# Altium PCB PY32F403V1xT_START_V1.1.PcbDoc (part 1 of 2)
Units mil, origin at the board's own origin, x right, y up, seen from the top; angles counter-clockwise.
Board outline 1771.65 x 2660.63 mil, 2 copper layers (Top Layer, Bottom Layer); 52 components, 105 nets, 324 pads, 111 vias.
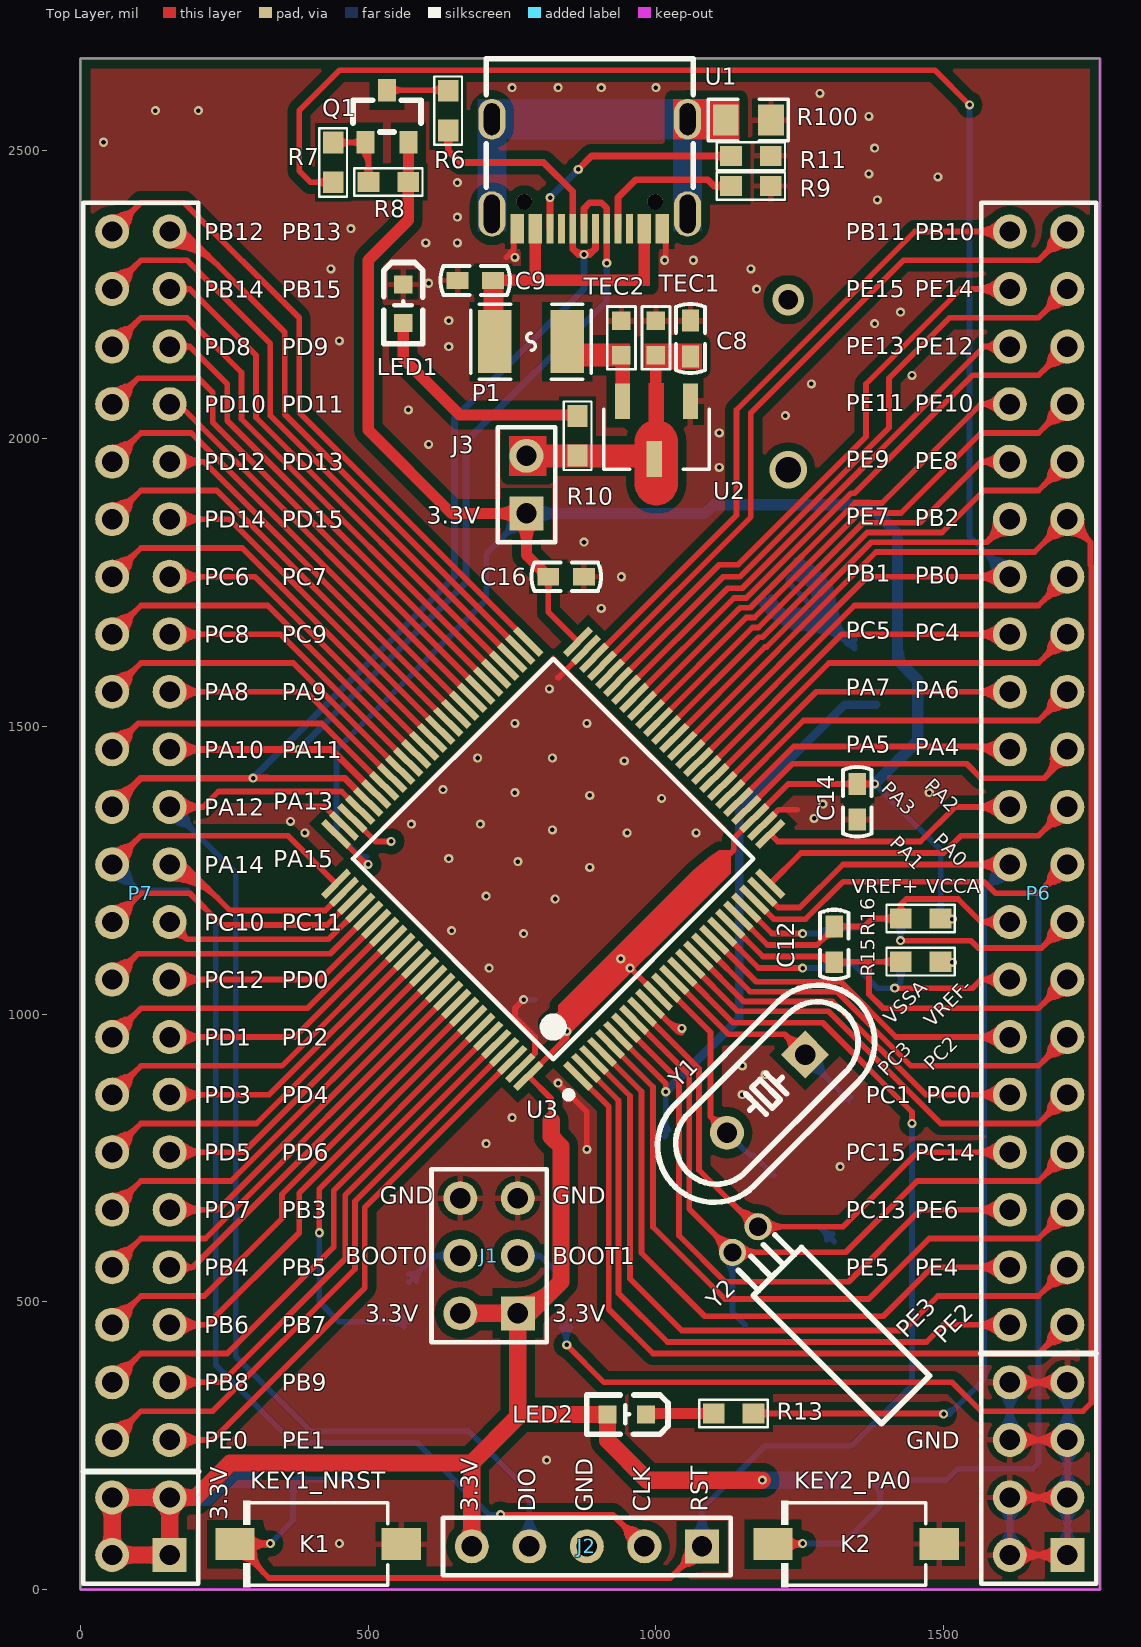
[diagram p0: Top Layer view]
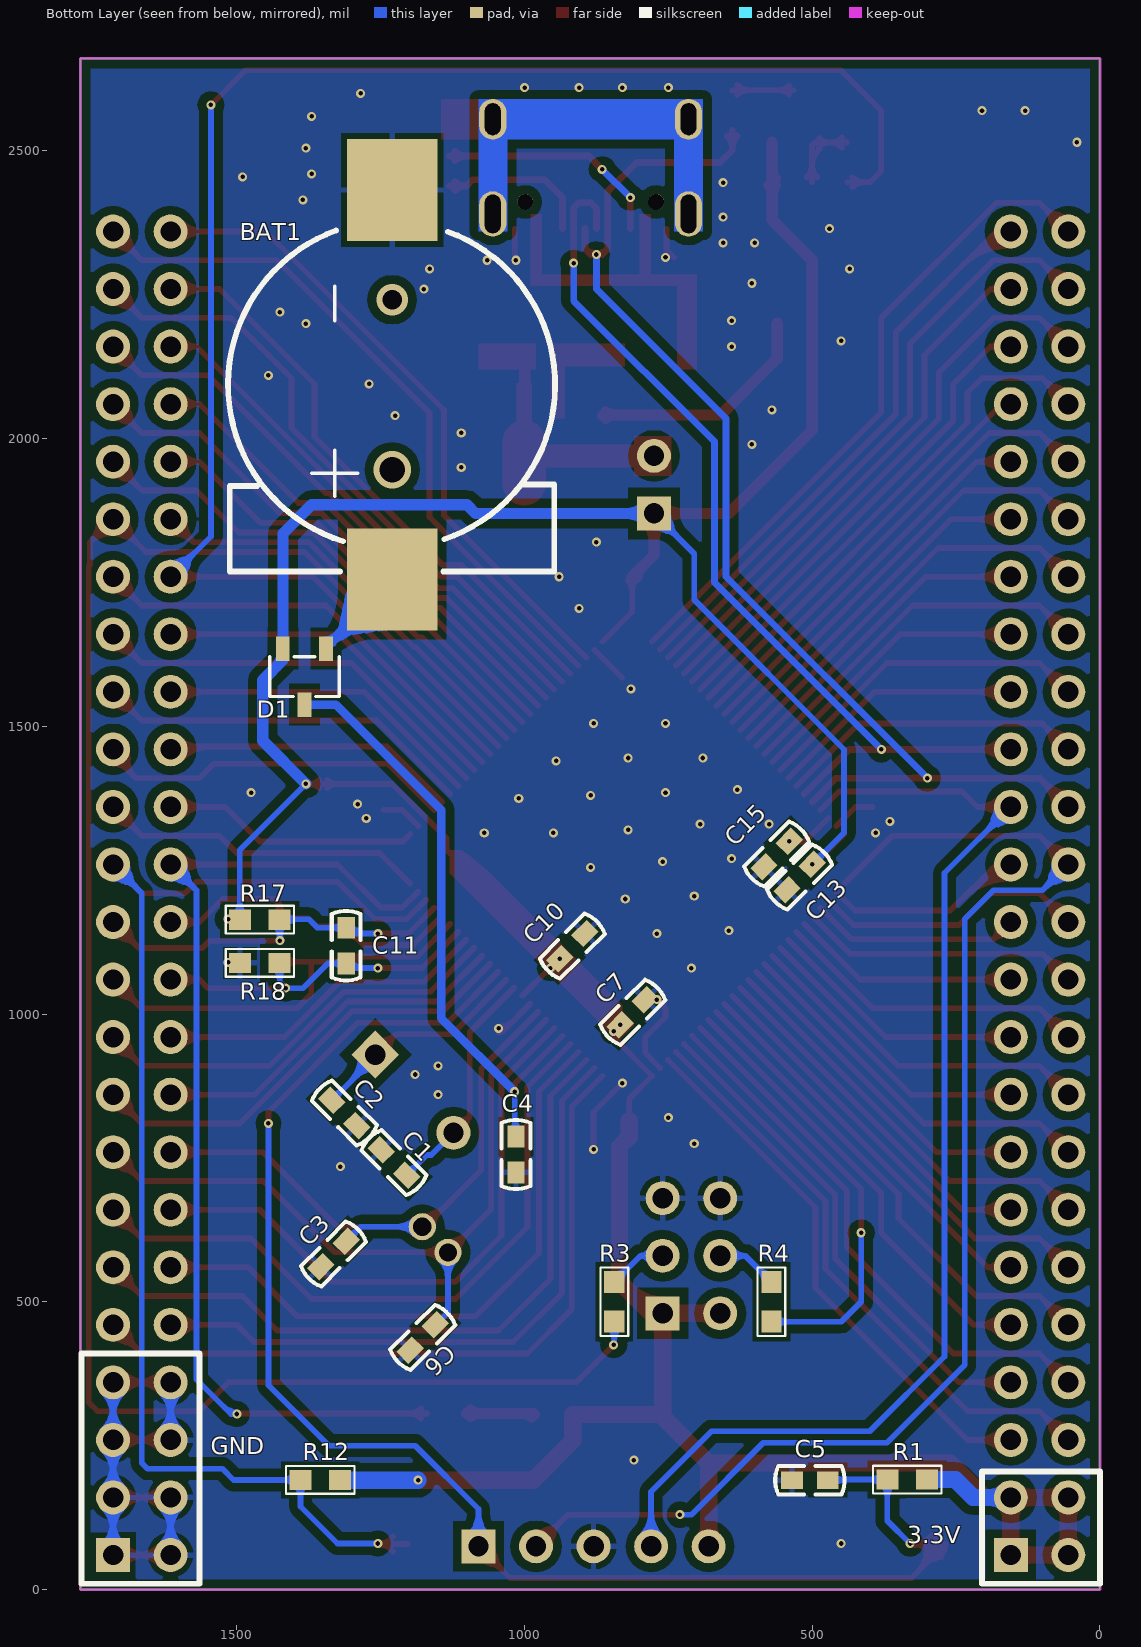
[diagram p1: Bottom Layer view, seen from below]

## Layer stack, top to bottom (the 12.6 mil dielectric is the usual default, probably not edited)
Top Layer: signal copper 1.4
Dielectric: dielectric 12.6, FR-4, Dk 4.8
Bottom Layer: signal copper 1.4

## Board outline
0,0 1771.65,0 1771.65,2660.63 0,2660.63

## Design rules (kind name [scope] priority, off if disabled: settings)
Clearance [All] p1: gap=7
ComponentClearance [All] p1: gap=0 collisioncheckmode=3 verticalgap=0 showdistances=FALSE
HoleSize [All] p1: absolutevalues=TRUE maxlimit=100 minlimit=0 maxpercent=80.000 minpercent=20.000
HoleToHoleClearance [All] p1: gap=0 allowstackedmicrovias=TRUE
MinimumSolderMaskSliver [All] p1: minsoldermaskwidth=0
PolygonConnect PolygonConnect_1 [IsVia] p1: connectstyle=Direct reliefconductorwidth=10 reliefentries=4 polygonreliefangle="90 Angle" airgapwidth=10
PolygonConnect [All] p2: connectstyle=Relief reliefconductorwidth=10 reliefentries=4 polygonreliefangle="90 Angle" airgapwidth=10
RoutingVias [All] p1: holewidth=7.87 width=15.75 viastyle="Through Hole" minholewidth=7.87 minwidth=15.75 maxholewidth=28 maxwidth=50
SilkToSilkClearance [All] p1: silktosilkclearance=0
SilkToSolderMaskClearance [IsPad] p1: minsilkscreentomaskgap=0 clearancetoexposedcopper=TRUE
SolderMaskExpansion [All] p1: expansion=4
Width [All] p1: maxlimit=393.7 minlimit=8 preferedwidth=10
22 further rules are at their usual default settings.

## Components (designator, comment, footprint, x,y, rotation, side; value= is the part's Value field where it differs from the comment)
BAT1 "KH-BS2032-2-1" bat2 1230,2240 r90 bottom
C1 "22pF" c0603cap 1205,720 r315 bottom
C2 "22pF" c0603cap 1335,850 r135 bottom
C3 "22pF" c0603cap 1310,605 r225 bottom
C4 "Cap" c0603cap 1015,725 r0 bottom
C5 "100nF" c0603cap 535,190 r90 bottom
C6 "22pF" c0603cap 1155,460 r225 bottom
C7 "100nF" c0603cap 790,1025 r225 bottom
C8 "0.1uF/50V" c0603cap 1060,2205 r0 top
C9 "0.1uF/50V" c0603cap 655,2275 r90 top
C10 "100nF" c0603cap 895,1140 r225 bottom
C11 "100nF" c0603cap 1310,1150 r180 bottom
C12 "100nF" c0603cap 1310,1090 r180 top
C13 "100nF" c0603cap 500,1260 r225 bottom
C14 "100nF" c0603cap 1350,1400 r0 top
C15 "100nF" c0603cap 540,1300 r225 bottom
C16 "100nF" c0603cap 875,1760 r270 top
D1 "BAT54C_C2135" 肖特基二极管、 1345,1635 r90 bottom
J1 "Header 3X2" HDR2X3 760,480 r90 top
J2 "Header 5" HDR1X5 1080,75 r180 top
J3 "JUMP" HDR1X2 775,1870 r90 top
K1 "1TS002B-2600-5001_key" SW 460,80 r180 top
K2 "1TS002B-2600-5001_key" SW 1395,80 r180 top
LED1 "RED" 0603_LED 560,2220 r270 top
LED2 "GREEN" 0603_LED 935,305 r180 top
P1 "SMD1210P005TF" SDM1210P005TF 780,2190 r0 top
P6 "Header 24X2" HDR2X24 1715,60 r90 top
P7 "Header 24X2" HDR2X24 155,60 r90 top
Q1 "2301" "SOT23 2301" 495.2,2515 r270 top
R1 "Res" 0603R 335,190 r180 bottom
R3 "Res" 0603R 845,500 r270 bottom
R4 "Res" 0603R 570,500 r90 bottom
R6 "Res" 0603R 640,2570 r90 top
R7 "Res" 0603R 440.2,2480 r90 top
R8 "Res" 0603R 535,2445 r0 top
R9 "5.1K" 0603R 1165,2440 r180 top
R10 "470Ω" 0603R 865,2005 r90 top
R11 "5.1K" 0603R 1165,2490 r0 top
R12 "1K" 0603R 1355,191.48 r0 bottom
R13 "680Ω" 0603R 1135,305 r0 top
R15 "Res" 0603R 1460,1090 r0 top
R16 "Res" 0603R 1460,1165 r0 top
R17 "Res" 0603R 1460,1165 r0 bottom
R18 "Res" 0603R 1460,1090 r0 bottom
R100 "Res" 0805 1155,2555 r180 top
TEC1 "10uF" 0603 1000,2175 r270 top
TEC2 "10uF" 0603 940,2175 r270 top
U1 "KH-TYPE-C-16P" USB-C-SMD_KH-TYPE-C-16P 885,2460 r180 top
U2 "LM1117-3.3" LM1117-3.3 1060,2065 r90 top
U3 "PY32F403vx" "100PIN LQFP" 805,1245 r45 top locked
Y1 "24M" 25MHZ_2 1165,840 r225 top
Y2 "32.768KHz" 32768KHZ_2 1240,517.86 r135 top

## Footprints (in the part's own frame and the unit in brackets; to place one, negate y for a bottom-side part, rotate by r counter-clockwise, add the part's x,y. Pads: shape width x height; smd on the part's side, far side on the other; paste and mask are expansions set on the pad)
25MHZ_2 [mm]
  rect 1.5x1.5 hole 0.9: 1(-3.302,0.087)
  round 1.5 hole 0.9: 2(1.578,0.087)
  silkscreen extent -6.6,-2.41 4.88,2.59
"100PIN LQFP" [mm]
  rect 0.3x1.6 smd: 1(-5.259,-7.401) 2(-4.76,-7.401) 3(-4.259,-7.401) 4(-3.76,-7.401) 5(-3.259,-7.401) 6(-2.76,-7.401) 7(-2.259,-7.401) 8(-1.76,-7.401) 9(-1.259,-7.401) 10(-0.76,-7.401) 11(-0.259,-7.401) 12(0.241,-7.401) 13(0.741,-7.401) 14(1.241,-7.401) 15(1.741,-7.401) 16(2.241,-7.401) 17(2.741,-7.401) 18(3.241,-7.401) 19(3.741,-7.401) 20(4.241,-7.401) 21(4.741,-7.401) 22(5.241,-7.401) 23(5.741,-7.401) 24(6.241,-7.401) 25(6.741,-7.401) 51(6.741,7.699) 52(6.241,7.699) 53(5.741,7.699) 54(5.241,7.699) 55(4.741,7.699) 56(4.241,7.699) 57(3.741,7.699) 58(3.241,7.699) 59(2.741,7.699) 60(2.241,7.699) 61(1.741,7.699) 62(1.241,7.699) 63(0.741,7.699) 64(0.241,7.699) 65(-0.259,7.699) 66(-0.76,7.699) 67(-1.259,7.699) 68(-1.76,7.699) 69(-2.259,7.699) 70(-2.76,7.699) 71(-3.259,7.699) 72(-3.76,7.699) 73(-4.259,7.699) 74(-4.76,7.699) 75(-5.259,7.699)
  rect 1.6x0.3 smd: 26(8.29,-5.851) 27(8.29,-5.351) 28(8.29,-4.851) 29(8.29,-4.351) 30(8.29,-3.851) 31(8.29,-3.351) 32(8.29,-2.851) 33(8.29,-2.351) 34(8.29,-1.851) 35(8.29,-1.351) 36(8.29,-0.851) 37(8.29,-0.351) 38(8.29,0.149) 39(8.29,0.649) 40(8.29,1.149) 41(8.29,1.649) 42(8.29,2.149) 43(8.29,2.649) 44(8.29,3.149) 45(8.29,3.649) 46(8.29,4.149) 47(8.29,4.649) 48(8.29,5.149) 49(8.29,5.649) 50(8.29,6.149) 76(-6.809,6.149) 77(-6.809,5.649) 78(-6.809,5.149) 79(-6.809,4.649) 80(-6.809,4.149) 81(-6.809,3.649) 82(-6.809,3.149) 83(-6.809,2.649) 84(-6.809,2.149) 85(-6.809,1.649) 86(-6.809,1.149) 87(-6.809,0.649) 88(-6.809,0.149) 89(-6.809,-0.351) 90(-6.809,-0.851) 91(-6.809,-1.351) 92(-6.809,-1.851) 93(-6.809,-2.351) 94(-6.809,-2.851) 95(-6.809,-3.351) 96(-6.809,-3.851) 97(-6.809,-4.351) 98(-6.809,-4.851) 99(-6.809,-5.351) 100(-6.809,-5.851)
  silkscreen extent -6.29,-7.85 6.99,6.4
0603 [mil]
  rect 32x32 smd: 1(30,0) 2(-30,0)
  silkscreen extent -54,-25 55,25
0603_LED [mil]
  rect 31.5x31.5 smd: 1(19,1) 2(-48,1)
  silkscreen extent -86,-33 55,35
0603R [mil]
  rect 38x35 smd: 1(-34.5,1) 2(34.5,1)
  silkscreen extent -59,-23 59,25, body extent -31,-15 32,17, height 18
0805 [mil]
  rect 44.59x54.21 smd mask+2: 1(-45.03,1.11) 2(33.71,1.11)
  silkscreen extent -75,-35 64,37
32768KHZ_2 [mm]
  round 1.2 hole 0.8: 1(3.142,-0.903) 2(3.142,0.697)
  silkscreen extent -6.86,-1.6 2.44,1.4
bat2 [mm]
  rect 4.5x4 smd mask+0.051: 1(-12.319,0) 2(4.881,0)
  silkscreen extent -11.96,-7.19 3.09,7.24
c0603cap [mil]
  rect 30x38 smd: 1(0,0) 2(0,-62)
  silkscreen extent -25,-91 25,29
HDR1X2 [mm] "Connector; Header; 2 Position"
  rect 1.5x1.5 hole 0.9: 1(0,0)
  round 1.5 hole 0.9: 2(2.54,0)
  silkscreen extent -1.27,-1.27 3.81,1.27
HDR1X5 [mm] "Connector; Header; 5 Position"
  rect 1.5x1.5 hole 0.9: 1(0,0)
  round 1.5 hole 0.9: 2(2.54,0) 3(5.08,0) 4(7.62,0) 5(10.16,0)
  silkscreen extent -1.27,-1.27 11.43,1.27
HDR2X3 [mm] "Connector; Header; 3x2 Position"
  rect 1.5x1.5 hole 0.9: 1(0,0)
  round 1.5 hole 0.9: 2(0,2.54) 3(2.54,0) 4(2.54,2.54) 5(5.08,0) 6(5.08,2.54)
  silkscreen extent -1.27,-1.27 6.35,3.81
HDR2X24 [mm] "Connector; Header; 24x2 Position"
  rect 1.5x1.5 hole 0.9: 1(0,0)
  round 1.5 hole 0.9: 2(0,2.54) 3(2.54,0) 4(2.54,2.54) 5(5.08,0) 6(5.08,2.54) 7(7.62,0) 8(7.62,2.54) 9(10.16,0) 10(10.16,2.54) 11(12.7,0) 12(12.7,2.54) 13(15.24,0) 14(15.24,2.54) 15(17.78,0) 16(17.78,2.54) 17(20.32,0) 18(20.32,2.54) 19(22.86,0) 20(22.86,2.54) 21(25.4,0) 22(25.4,2.54) 23(27.94,0) 24(27.94,2.54) 25(30.48,0) 26(30.48,2.54) 27(33.02,0) 28(33.02,2.54) 29(35.56,0) 30(35.56,2.54) 31(38.1,0) 32(38.1,2.54) 33(40.64,0) 34(40.64,2.54) 35(43.18,0) 36(43.18,2.54) 37(45.72,0) 38(45.72,2.54) 39(48.26,0) 40(48.26,2.54) 41(50.8,0) 42(50.8,2.54) 43(53.34,0) 44(53.34,2.54) 45(55.88,0) 46(55.88,2.54) 47(58.42,0) 48(58.42,2.54)
  silkscreen extent -1.27,-1.27 59.69,3.81
LM1117-3.3 [mm]
  rect 1.575x0.672 smd: 1(0,0) 2(-2.55,1.598) 3(0,3)
  Top Layer region: -3.64,2.459 -1.785,2.459 -1.741,2.458 -1.696,2.455 -1.652,2.449 -1.608,2.442 -1.565,2.433 -1.522,2.421 -1.479,2.408 -1.437,2.393 -1.396,2.375 -1.356,2.356 -1.317,2.335 -1.279,2.312 -1.241,2.288 -1.206,2.261 -1.171,2.233 -1.138,2.204 -1.106,2.173 -1.075,2.14 -1.047,2.106 -1.019,2.071 -0.994,2.034 -0.97,1.996 -0.948,1.958 -0.928,1.918 -0.91,1.839 0.788,1.839 0.788,1.179 -0.91,1.179 -0.928,1.099 -0.948,1.06 -0.97,1.021 -0.994,0.983 -1.019,0.947 -1.047,0.911 -1.075,0.877 -1.106,0.845 -1.138,0.814 -1.171,0.784 -1.206,0.756 -1.241,0.73 -1.279,0.705 -1.317,0.682 -1.356,0.661 -1.396,0.642 -1.437,0.625 -1.479,0.609 -1.522,0.596 -1.565,0.585 -1.608,0.575 -1.652,0.568 -1.696,0.563 -1.741,0.56 -1.785,0.559 -3.64,0.559 -3.684,0.56 -3.728,0.563 -3.773,0.568 -3.817,0.575 -3.86,0.585 -3.903,0.596 -3.946,0.609 -3.988,0.625 -4.029,0.642 -4.069,0.661 -4.108,0.682 -4.146,0.705 -4.183,0.73 -4.219,0.756 -4.254,0.784 -4.287,0.814 -4.319,0.845 -4.349,0.877 -4.378,0.911 -4.405,0.947 -4.431,0.983 -4.455,1.021 -4.477,1.06 -4.497,1.099 -4.515,1.14 -4.531,1.181 -4.546,1.224 -4.558,1.266 -4.568,1.31 -4.577,1.353 -4.583,1.398 -4.587,1.442 -4.589,1.486 -4.589,1.531 -4.587,1.575 -4.583,1.62 -4.577,1.664 -4.568,1.708 -4.558,1.751 -4.546,1.794 -4.531,1.836 -4.515,1.877 -4.497,1.918 -4.477,1.958 -4.455,1.996 -4.431,2.034 -4.405,2.071 -4.378,2.106 -4.349,2.14 -4.319,2.173 -4.287,2.204 -4.254,2.233 -4.219,2.261 -4.183,2.288 -4.146,2.312 -4.108,2.335 -4.069,2.356 -4.029,2.375 -3.988,2.393 -3.946,2.408 -3.903,2.421 -3.86,2.433 -3.817,2.442 -3.773,2.449 -3.728,2.455 -3.684,2.458
  silkscreen extent -3.01,-0.83 -0.35,3.83
SDM1210P005TF [mm]
  rect 1.485x2.781 smd: 1(-1.524,-0.549) 2(1.676,-0.549)
  silkscreen extent -2.59,-2.2 2.74,1.1
"SOT23 2301" [mm]
  rect 1x0.8 smd mask+0.051: 1(0,0) 2(0,1.9) 3(-2.3,0.95)
  silkscreen extent -1.85,-0.55 -0.45,2.45
SW [mm]
  rect 1.74x1.4 smd: 1(-2.476,0.024) 2(4.864,0.024)
  silkscreen extent -1.88,-1.88 4.5,1.93
USB-C-SMD_KH-TYPE-C-16P [mm]
  oval 1.2x2 hole 0.7 slot 1.7 at 90 deg: 1(-4.32,1.765) 2(4.32,1.765)
  oval 1.2x1.8 hole 0.7 slot 1.4 at 90 deg: 3(-4.32,-2.415) 4(4.32,-2.415)
  rect 0.3x1.3 smd: A1(-3.35,2.415) A4(-2.55,2.415) A5(-1.25,2.415) A6(-0.25,2.415) A7(0.25,2.415) A8(1.25,2.415) A9(2.55,2.415) A12(3.35,2.415) B1(3.05,2.415) B4(2.25,2.415) B5(1.75,2.415) B6(0.75,2.415) B7(-0.75,2.415) B8(-1.75,2.415) B9(-2.25,2.415) B12(-3.05,2.415)
  round 0.7 hole 0.7 unplated: ""(-2.89,1.235) ""(2.89,1.235)
  silkscreen extent -4.57,-5.08 4.57,0.57
肖特基二极管、 [mm]
  rect 1.07x0.6 smd mask+0.051: 1(0,0) 2(0,1.9) 3(-2.47,0.95)
  silkscreen extent -2.11,-0.59 -0.36,2.49

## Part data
C1 C2 C3 C5 C6 C7 C10 C11 C12 C13 C14 C15 C16: library part C0603
C4: "Capacitor"
C8: library part Cap, "Capacitor"
C9: library part CAP, "Capacitor"
J1: "Header, 3-Pin, Dual row"
J2: "Header, 5-Pin"
LED1 LED2: library part PDI-E803_Dup1
P6 P7: "Header, 24-Pin, Dual row"
Q1: library part "MOSFET P", "MOSFET P"
R1 R3 R4 R6 R7 R8 R15 R16 R17 R18 R100: "Resistor"
R9 R11: library part Res_1, "Resistor"
R10 R12 R13: library part Res, "Resistor"
TEC1 TEC2: library part 贴片钽电容
U3: library part PY32F403vx_LQFP100
Y1: library part CRYSTAL, "Crystal"
Y2: library part CRYSTAL_1, "Crystal"

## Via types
v1: diameter 15.75, hole 7.87, Top Layer to Bottom Layer, 109 vias
v2: diameter 65, hole 44, Top Layer to Bottom Layer, 1 vias
v3: diameter 55, hole 34, Top Layer to Bottom Layer, 1 vias

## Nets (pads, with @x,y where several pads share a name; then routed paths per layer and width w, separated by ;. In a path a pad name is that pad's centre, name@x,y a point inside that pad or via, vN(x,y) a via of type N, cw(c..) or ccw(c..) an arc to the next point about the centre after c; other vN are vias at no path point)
3.3V: C7.2 C10.2 C13.1 C14.1 C16.2 D1.2 J1.1 J1.2 J2.5 J3.1 LED2.1 P7.1 P7.2 P7.3 P7.4 Q1.2 R1.2 R8.2 R12.1 R16.2 R17.2 U3.11 U3.28 U3.50 U3.75 U3.100 | length 10358.9
  Top Layer w10: U3.75@444.26,1312.91 497.17,1260 v1(500,1260) ; 488.47,1265.96 cw(c484.8,1252.27) v1@497.44,1258.7 ; C16.2@813,1760 813,1698.6 U3.50@864.62,1646.97 ; 818,815 818,852.87 U3.100@778.33,892.54 845,959.21 v1(845,970) v1(955,1080) ; 838.79,957.54 cw(c854.65,953.29) v1@846.44,967.51 ; U3.11@1003.82,1031.74 955.56,1080 v1(955,1080) ; C14.1@1345,1400 1230.11,1400 U3.28@1170.85,1340.74 1135.11,1305 1135.11,1285.11 1120,1270 1120,1245 v1(955,1080) ; C14.1@1350,1400 v1(1380,1400) ; 813,1735.86 cw(c837.14,1735.86) 820.07,1752.93 ccw(c837.14,1735.86) 813,1735.86 ; 813,1735.86 ccw(c788.86,1735.86) 805.93,1752.93 cw(c788.86,1735.86) 813,1735.86 ; 1325.86,1400 cw(c1325.86,1375.86) 1342.93,1392.93 ccw(c1325.86,1375.86) 1325.86,1400 ; 1325.86,1400 ccw(c1325.86,1424.14) 1342.93,1407.07 cw(c1325.86,1424.14) 1325.86,1400 ; 1369.37,1398.72 cw(c1372.51,1387.02) v1@1378.56,1397.51 ; 1369.37,1398.72 cw(c1372.51,1387.02) v1@1378.56,1397.51 ; 1369.37,1398.72 cw(c1372.51,1387.02) v1@1378.56,1397.51 ; 1369.37,1401.28 ccw(c1372.51,1412.98) v1@1378.56,1402.49 ; 1369.37,1401.28 ccw(c1372.51,1412.98) v1@1378.56,1402.49 ; 1369.37,1401.28 ccw(c1372.51,1412.98) v1@1378.56,1402.49 ; v1@1374.14,1400 cw(c1374.14,1424.14) 1357.07,1407.07 ccw(c1374.14,1424.14) v1@1374.14,1400 ; v1@1374.14,1400 ccw(c1374.14,1375.86) 1357.07,1392.93 cw(c1374.14,1375.86) v1@1374.14,1400 ; 490.26,1266.91 ccw(c500,1276.65) 500,1262.87 cw(c500,1276.65) 490.26,1266.91 ; 832.47,946.68 ccw(c809.15,970) 842.13,970 cw(c809.15,970) 832.47,946.68 ; v1@955,1077.13 cw(c955,1068.84) 960.86,1074.7 ccw(c955,1068.84) v1@955,1077.13
  Top Layer w19.68: Q1.2@570,2515 570,2446.5 R8.2@569.5,2446 569.5,2379.5 500,2310 500,2015 645,1870 J3.1@775,1870 775,1798 C16.2@813,1760 ; 569.5,2427.51 cw(c587.99,2427.51) 574.91,2440.59 ccw(c587.99,2427.51) 569.5,2427.51 ; 569.5,2427.51 ccw(c551.01,2427.51) 564.09,2440.59 cw(c551.01,2427.51) 569.5,2427.51 ; 727.48,1870 cw(c727.48,1822.48) J3.1@761.08,1856.08 ; 727.48,1870 ccw(c727.48,1917.52) 761.08,1883.92 cw(c727.48,1917.52) 727.48,1870 ; 727.48,1870 cw(c727.48,1822.48) J3.1@761.08,1856.08 ; J3.1@761.08,1856.08 cw(c727.48,1822.48) 775,1822.48 ; J3.1@761.08,1856.08 cw(c727.48,1822.48) 775,1822.48 ; 775,1822.48 cw(c822.52,1822.48) 788.92,1856.08 ccw(c822.52,1822.48) 775,1822.48 ; R8.2@564.09,2451.41 ccw(c549.81,2465.69) 570,2465.69 cw(c549.81,2465.69) R8.2@564.09,2451.41 ; 797.37,1775.63 cw(c781.73,1760) 803.84,1760 ccw(c781.73,1760) 797.37,1775.63
  Top Layer w30: P7.2@55,60 P7.2@55,65 ; J1.2@660,480 J1.1@760,480 ; J2.5@680,75 680,220 ; 818,815 818,787 835,770 835,535 780,480 J1.1@760,480 ; v1(1185,190) 985,190 916,259 LED2.1@916,304 764,304 760,300 ; P7.2@55,65 P7.4@55,160 P7.3@155,160 ; P7.2@55,65 60,60 P7.1@155,60 P7.3@155,160 ; 55,95.07 cw(c19.93,95.07) 44.73,70.27 ccw(c19.93,95.07) 55,95.07 ; 55,95.07 ccw(c90.07,95.07) P7.2@65.27,70.27 ; 55,95.07 ccw(c90.07,95.07) P7.2@65.27,70.27 ; 55,124.93 cw(c90.07,124.93) P7.4@65.27,149.73 ; 55,124.93 ccw(c19.93,124.93) 44.73,149.73 cw(c19.93,124.93) 55,124.93 ; 55,124.93 cw(c90.07,124.93) P7.4@65.27,149.73 ; P7.2@65.27,70.27 ccw(c90.07,95.07) 90.07,60 ; P7.2@65.27,70.27 ccw(c90.07,95.07) 90.07,60 ; P7.4@65.27,149.73 cw(c90.07,124.93) 90.07,160 ; P7.4@65.27,149.73 cw(c90.07,124.93) 90.07,160 ; 90.07,60 ccw(c90.07,24.93) 65.27,49.73 cw(c90.07,24.93) 90.07,60 ; 90.07,160 cw(c90.07,195.07) 65.27,170.27 ccw(c90.07,195.07) 90.07,160 ; 119.93,60 cw(c119.93,24.93) 144.73,49.73 ccw(c119.93,24.93) 119.93,60 ; 119.93,60 ccw(c119.93,95.07) P7.1@144.73,70.27 ; 119.93,60 ccw(c119.93,95.07) P7.1@144.73,70.27 ; 119.93,160 cw(c119.93,124.93) P7.3@144.73,149.73 ; 119.93,160 ccw(c119.93,195.07) 144.73,170.27 cw(c119.93,195.07) 119.93,160 ; 119.93,160 cw(c119.93,124.93) P7.3@144.73,149.73 ; P7.1@144.73,70.27 ccw(c119.93,95.07) 155,95.07 ; P7.1@144.73,70.27 ccw(c119.93,95.07) 155,95.07 ; P7.3@144.73,149.73 cw(c119.93,124.93) 155,124.93 ; P7.3@144.73,149.73 cw(c119.93,124.93) 155,124.93 ; 155,95.07 ccw(c190.07,95.07) 165.27,70.27 cw(c190.07,95.07) 155,95.07 ; 155,124.93 cw(c190.07,124.93) P7.3@165.27,149.73 ; 155,124.93 cw(c190.07,124.93) P7.3@165.27,149.73 ; P7.3@155,160 200,160 260,220 680,220 ; P7.3@165.27,149.73 cw(c190.07,124.93) 190.07,160 ; P7.3@165.27,149.73 cw(c190.07,124.93) 190.07,160 ; 190.07,160 cw(c190.07,195.07) 165.27,170.27 ccw(c190.07,195.07) 190.07,160 ; 680,110.07 cw(c644.93,110.07) 669.73,85.27 ccw(c644.93,110.07) 680,110.07 ; 680,110.07 ccw(c715.07,110.07) 690.27,85.27 cw(c715.07,110.07) 680,110.07 ; 680,220 760,300 ; 695.07,480 cw(c695.07,515.07) 670.27,490.27 ccw(c695.07,515.07) 695.07,480 ; 695.07,480 ccw(c695.07,444.93) 670.27,469.73 cw(c695.07,444.93) 695.07,480 ; 724.93,480 cw(c724.93,444.93) J1.1@749.73,469.73 ; 724.93,480 ccw(c724.93,515.07) 749.73,490.27 cw(c724.93,515.07) 724.93,480 ; 724.93,480 cw(c724.93,444.93) J1.1@749.73,469.73 ; J1.1@749.73,469.73 cw(c724.93,444.93) 760,444.93 ; J1.1@749.73,469.73 cw(c724.93,444.93) 760,444.93 ; 760,300 J1.1@760,480 ; 760,444.93 cw(c795.07,444.93) 770.27,469.73 ccw(c795.07,444.93) 760,444.93 ; J1.1@760,494.53 ccw(c760,577.88) 818.94,518.94 cw(c760,577.88) J1.1@760,494.53
  Bottom Layer w10: v1(500,1260) 445,1315 445,1460 705,1720 705,1800 J3.1@775,1870 ; 744.48,1847.65 cw(c781.61,1837.7) J3.1@773.9,1875.36 ; 752.65,1839.48 ccw(c742.7,1876.61) J3.1@780.36,1868.9 ; v1(833.84,981.16) v1(845,970) ; v1(938.84,1096.16) v1(955,1080) ; v1(1380,1400) 1495,1285 1495,1164.5 R17.2@1494.5,1164 ; 480.1,1279.9 cw(c463.03,1262.83) 487.17,1262.83 ccw(c463.03,1262.83) 480.1,1279.9 ; 480.1,1279.9 ccw(c497.17,1296.97) 497.17,1272.83 cw(c497.17,1296.97) 480.1,1279.9 ; 733.13,1828.13 cw(c775,1786.26) 775,1845.47 ccw(c775,1786.26) 733.13,1828.13 ; 733.13,1828.13 ccw(c691.26,1870) 750.47,1870 cw(c691.26,1870) 733.13,1828.13 ; J3.1@750.2,1845.2 cw(c775,1820.4) 775,1855.47 ccw(c775,1820.4) J3.1@750.2,1845.2 ; J3.1@750.2,1845.2 ccw(c725.4,1870) 760.47,1870 cw(c725.4,1870) J3.1@750.2,1845.2 ; R17.2@1485.66,1172.84 ccw(c1463.12,1195.38) 1495,1195.38 cw(c1463.12,1195.38) R17.2@1485.66,1172.84 ; 1495,1192.97 ccw(c1523.47,1192.97) 1503.34,1172.84 cw(c1523.47,1192.97) 1495,1192.97
  Bottom Layer w19.68: J3.1@775,1870 1085,1870 1100,1885 1370,1885 1419.8,1835.2 D1.2@1419.8,1635 1419.8,1615.2 1455,1580 1455,1475 v1(1380,1400) ; 822.52,1870 cw(c822.52,1917.52) 788.92,1883.92 ccw(c822.52,1917.52) 822.52,1870 ; 822.52,1870 ccw(c822.52,1822.48) 788.92,1856.08 cw(c822.52,1822.48) 822.52,1870 ; D1.2@1421.77,1625.75 ccw(c1451.99,1625.75) 1430.62,1604.38 cw(c1451.99,1625.75) D1.2@1421.77,1625.75
  Bottom Layer w30: P7.3@155,160 220,160 251,191 R1.2@300.5,191 ; v1(1185,190) 1320.02,190 R12.1@1320.5,190.48 ; 190.07,160 cw(c190.07,195.07) 165.27,170.27 ccw(c190.07,195.07) 190.07,160 ; 190.07,160 ccw(c190.07,124.93) 165.27,149.73 cw(c190.07,124.93) 190.07,160
  other v1: 1515,1165
BOOT0: R4.1 U3.94 | length 857
  Top Layer w10.02: v1(415,620) 415,696.25 U3.94@694.81,976.06
  Bottom Layer w10.02: v1(415,620) 415,500 449.5,465.5 R4.1@571,465.5 ; 540.85,465.5 cw(c540.85,435.35) 562.17,456.67 ccw(c540.85,435.35) 540.85,465.5 ; 540.85,465.5 ccw(c540.85,495.65) 562.17,474.33 cw(c540.85,495.65) 540.85,465.5
GND: BAT1.2 C1.2 C2.2 C3.2 C4.1 C5.1 C6.2 C7.1 C8.1 C9.1 C10.1 C13.2 C14.2 C15.2 C16.1 J1.5 J1.6 J2.3 K1.1 K2.1 LED1.2 P6.1 P6.2 P6.3 P6.4 P6.5 P6.6 P6.7 P6.8 R9.1 R11.2 R15.2 R18.2 R100.1 TEC1.2 TEC2.2 U1.A1 U1.A12 U1.B1 U1.B12 U2.1 U3.10 U3.27 U3.49 U3.74 U3.99 | length 6998.1
  Top Layer w10: 395,1360 425,1360 U3.74@458.18,1326.82 ; 740,2315 753.11,2328.11 U1.A12@753.11,2364.92 ; U3.99@764.41,906.46 790,932.05 790,960 755,995 755,1010 v1(770,1025) ; v1(830,880) 880,830 v1(880,765) ; 830,1585 830.49,1585 U3.49@878.54,1633.05 ; U3.10@989.9,1017.82 1032.71,975 v1(1045,975) ; v1(1015,2310) 1016.89,2311.89 U1.A1@1016.89,2364.92 ; 1019.12,988.6 ccw(c1045,1014.48) v1@1045,977.87 ; 1036.19,971.52 ccw(c1045,980.34) v1@1045,967.87 ; U3.27@1184.77,1326.82 1212.95,1355 1245,1355 ; P6.2@1615,60 P6.1@1715,60 ; P6.4@1615,160 P6.3@1715,160 ; P6.6@1615,260 P6.5@1715,260 ; P6.8@1615,360 P6.7@1715,360 ; 1650.07,60 cw(c1650.07,95.07) 1625.27,70.27 ccw(c1650.07,95.07) 1650.07,60 ; 1650.07,60 ccw(c1650.07,24.93) 1625.27,49.73 cw(c1650.07,24.93) 1650.07,60 ; 1650.07,160 cw(c1650.07,195.07) 1625.27,170.27 ccw(c1650.07,195.07) 1650.07,160 ; 1650.07,160 ccw(c1650.07,124.93) 1625.27,149.73 cw(c1650.07,124.93) 1650.07,160 ; 1650.07,260 cw(c1650.07,295.07) 1625.27,270.27 ccw(c1650.07,295.07) 1650.07,260 ; 1650.07,260 ccw(c1650.07,224.93) 1625.27,249.73 cw(c1650.07,224.93) 1650.07,260 ; 1650.07,360 cw(c1650.07,395.07) 1625.27,370.27 ccw(c1650.07,395.07) 1650.07,360 ; 1650.07,360 ccw(c1650.07,324.93) 1625.27,349.73 cw(c1650.07,324.93) 1650.07,360 ; 1655.79,60 cw(c1655.79,0.79) 1697.66,42.66 ccw(c1655.79,0.79) 1655.79,60 ; 1655.79,60 ccw(c1655.79,119.21) 1697.66,77.34 cw(c1655.79,119.21) 1655.79,60 ; 1655.79,160 cw(c1655.79,100.79) 1697.66,142.66 ccw(c1655.79,100.79) 1655.79,160 ; 1655.79,160 ccw(c1655.79,219.21) 1697.66,177.34 cw(c1655.79,219.21) 1655.79,160 ; 1655.79,260 cw(c1655.79,200.79) 1697.66,242.66 ccw(c1655.79,200.79) 1655.79,260 ; 1655.79,260 ccw(c1655.79,319.21) 1697.66,277.34 cw(c1655.79,319.21) 1655.79,260 ; 1655.79,360 cw(c1655.79,300.79) 1697.66,342.66 ccw(c1655.79,300.79) 1655.79,360 ; 1655.79,360 ccw(c1655.79,419.21) 1697.66,377.34 cw(c1655.79,419.21) 1655.79,360 ; 1674.21,60 cw(c1674.21,119.21) 1632.34,77.34 ccw(c1674.21,119.21) 1674.21,60 ; 1674.21,60 ccw(c1674.21,0.79) 1632.34,42.66 cw(c1674.21,0.79) 1674.21,60 ; 1674.21,160 cw(c1674.21,219.21) 1632.34,177.34 ccw(c1674.21,219.21) 1674.21,160 ; 1674.21,160 ccw(c1674.21,100.79) 1632.34,142.66 cw(c1674.21,100.79) 1674.21,160 ; 1674.21,260 cw(c1674.21,319.21) 1632.34,277.34 ccw(c1674.21,319.21) 1674.21,260 ; 1674.21,260 ccw(c1674.21,200.79) 1632.34,242.66 cw(c1674.21,200.79) 1674.21,260 ; 1674.21,360 cw(c1674.21,419.21) 1632.34,377.34 ccw(c1674.21,419.21) 1674.21,360 ; 1674.21,360 ccw(c1674.21,300.79) 1632.34,342.66 cw(c1674.21,300.79) 1674.21,360 ; 1679.93,60 cw(c1679.93,24.93) 1704.73,49.73 ccw(c1679.93,24.93) 1679.93,60 ; 1679.93,60 ccw(c1679.93,95.07) 1704.73,70.27 cw(c1679.93,95.07) 1679.93,60 ; 1679.93,160 cw(c1679.93,124.93) 1704.73,149.73 ccw(c1679.93,124.93) 1679.93,160 ; 1679.93,160 ccw(c1679.93,195.07) 1704.73,170.27 cw(c1679.93,195.07) 1679.93,160 ; 1679.93,260 cw(c1679.93,224.93) 1704.73,249.73 ccw(c1679.93,224.93) 1679.93,260 ; 1679.93,260 ccw(c1679.93,295.07) 1704.73,270.27 cw(c1679.93,295.07) 1679.93,260 ; 1679.93,360 cw(c1679.93,324.93) 1704.73,349.73 ccw(c1679.93,324.93) 1679.93,360 ; 1679.93,360 ccw(c1679.93,395.07) 1704.73,370.27 cw(c1679.93,395.07) 1679.93,360 ; v1@1012.97,2312.03 ccw(c1003.5,2321.5) 1016.89,2321.5 cw(c1003.5,2321.5) v1@1012.97,2312.03
  Bottom Layer w10: v1(770,1025) C7.1@790,1025 ; P6.2@1615,60 P6.4@1615,160 ; P6.6@1615,260 P6.8@1615,360 ; P6.1@1715,60 P6.3@1715,160 P6.5@1715,260 P6.7@1715,360 ; 1615,95.07 cw(c1579.93,95.07) 1604.73,70.27 ccw(c1579.93,95.07) 1615,95.07 ; 1615,95.07 ccw(c1650.07,95.07) 1625.27,70.27 cw(c1650.07,95.07) 1615,95.07 ; 1615,100.79 cw(c1674.21,100.79) 1632.34,142.66 ccw(c1674.21,100.79) 1615,100.79 ; 1615,100.79 ccw(c1555.79,100.79) 1597.66,142.66 cw(c1555.79,100.79) 1615,100.79 ; 1615,119.21 cw(c1555.79,119.21) 1597.66,77.34 ccw(c1555.79,119.21) 1615,119.21 ; 1615,119.21 ccw(c1674.21,119.21) 1632.34,77.34 cw(c1674.21,119.21) 1615,119.21 ; 1615,124.93 cw(c1650.07,124.93) 1625.27,149.73 ccw(c1650.07,124.93) 1615,124.93 ; 1615,124.93 ccw(c1579.93,124.93) 1604.73,149.73 cw(c1579.93,124.93) 1615,124.93 ; 1615,295.07 cw(c1579.93,295.07) 1604.73,270.27 ccw(c1579.93,295.07) 1615,295.07 ; 1615,295.07 ccw(c1650.07,295.07) 1625.27,270.27 cw(c1650.07,295.07) 1615,295.07 ; 1615,300.79 cw(c1674.21,300.79) 1632.34,342.66 ccw(c1674.21,300.79) 1615,300.79 ; 1615,300.79 ccw(c1555.79,300.79) 1597.66,342.66 cw(c1555.79,300.79) 1615,300.79 ; 1615,319.21 cw(c1555.79,319.21) 1597.66,277.34 ccw(c1555.79,319.21) 1615,319.21 ; 1615,319.21 ccw(c1674.21,319.21) 1632.34,277.34 cw(c1674.21,319.21) 1615,319.21 ; 1615,324.93 cw(c1650.07,324.93) 1625.27,349.73 ccw(c1650.07,324.93) 1615,324.93 ; 1615,324.93 ccw(c1579.93,324.93) 1604.73,349.73 cw(c1579.93,324.93) 1615,324.93 ; 1715,95.07 cw(c1679.93,95.07) 1704.73,70.27 ccw(c1679.93,95.07) 1715,95.07 ; 1715,95.07 ccw(c1750.07,95.07) 1725.27,70.27 cw(c1750.07,95.07) 1715,95.07 ; 1715,100.79 cw(c1774.21,100.79) 1732.34,142.66 ccw(c1774.21,100.79) 1715,100.79 ; 1715,100.79 ccw(c1655.79,100.79) 1697.66,142.66 cw(c1655.79,100.79) 1715,100.79 ; 1715,119.21 cw(c1655.79,119.21) 1697.66,77.34 ccw(c1655.79,119.21) 1715,119.21 ; 1715,119.21 ccw(c1774.21,119.21) 1732.34,77.34 cw(c1774.21,119.21) 1715,119.21 ; 1715,124.93 cw(c1750.07,124.93) 1725.27,149.73 ccw(c1750.07,124.93) 1715,124.93 ; 1715,124.93 ccw(c1679.93,124.93) 1704.73,149.73 cw(c1679.93,124.93) 1715,124.93 ; 1715,195.07 cw(c1679.93,195.07) 1704.73,170.27 ccw(c1679.93,195.07) 1715,195.07 ; 1715,195.07 ccw(c1750.07,195.07) 1725.27,170.27 cw(c1750.07,195.07) 1715,195.07 ; 1715,200.79 cw(c1774.21,200.79) 1732.34,242.66 ccw(c1774.21,200.79) 1715,200.79 ; 1715,200.79 ccw(c1655.79,200.79) 1697.66,242.66 cw(c1655.79,200.79) 1715,200.79 ; 1715,219.21 cw(c1655.79,219.21) 1697.66,177.34 ccw(c1655.79,219.21) 1715,219.21 ; 1715,219.21 ccw(c1774.21,219.21) 1732.34,177.34 cw(c1774.21,219.21) 1715,219.21 ; 1715,224.93 cw(c1750.07,224.93) 1725.27,249.73 ccw(c1750.07,224.93) 1715,224.93 ; 1715,224.93 ccw(c1679.93,224.93) 1704.73,249.73 cw(c1679.93,224.93) 1715,224.93 ; 1715,295.07 cw(c1679.93,295.07) 1704.73,270.27 ccw(c1679.93,295.07) 1715,295.07 ; 1715,295.07 ccw(c1750.07,295.07) 1725.27,270.27 cw(c1750.07,295.07) 1715,295.07 ; 1715,300.79 cw(c1774.21,300.79) 1732.34,342.66 ccw(c1774.21,300.79) 1715,300.79 ; 1715,300.79 ccw(c1655.79,300.79) 1697.66,342.66 cw(c1655.79,300.79) 1715,300.79 ; 1715,319.21 cw(c1655.79,319.21) 1697.66,277.34 ccw(c1655.79,319.21) 1715,319.21 ; 1715,319.21 ccw(c1774.21,319.21) 1732.34,277.34 cw(c1774.21,319.21) 1715,319.21 ; 1715,324.93 cw(c1750.07,324.93) 1725.27,349.73 ccw(c1750.07,324.93) 1715,324.93 ; 1715,324.93 ccw(c1679.93,324.93) 1704.73,349.73 cw(c1679.93,324.93) 1715,324.93
  other v1: 450,80 810,225 1320,735 705,775 750,820 1150,860 1190,895 1150,910 710,1080 1515,1090 770,1140 645,1145 825,1200 705,1205 885,1255 760,1265 640,1270 390,1315 950,1315 1070,1315 820,1320 575,1330 695,1330 365,1335 1275,1340 1290,1365 1010,1375 885,1380 755,1385 1475,1385 630,1390 945,1440 690,1445 820,1445 755,1505 880,1505 815,1565 905,1705 940,1760 875,1820 1110,1950 605,1990 1110,2010 1225,2040 570,2050 1270,2095 1445,2110 640,2160 450,2170 1380,2200 640,2205 1425,2220 1175,2260 605,2270 435,2295 1165,2295 1065,2310 755,2315 600,2340 655,2340 470,2365 655,2385 1385,2415 655,2445 1490,2455 1370,2460 1380,2505 40,2515 1370,2560 130,2570 205,2570 1285,2600 750,2610 830,2610 905,2610 1000,2610
NetBAT1_1: BAT1.1 D1.1 | length 2640.5
  Bottom Layer w10: BAT1.1@1183.19,1713.95 ccw(c1267.59,1770.22) BAT1.1@1252.98,1669.83 ; BAT1.1@1191.51,1719.5 ccw(c1292.71,1786.96) BAT1.1@1275.19,1666.6 ; BAT1.1@1199.83,1725.05 ccw(c1317.83,1803.7) 1297.4,1663.37 ; BAT1.1@1230,1755 1230,1750 D1.1@1345,1635 ; BAT1.1@1234.73,1760.71 cw(c1198.7,1642.29) 1319.63,1668.74 ; BAT1.1@1237.64,1770.28 cw(c1204.4,1661) 1315.98,1685.41 ; BAT1.1@1240.55,1779.85 cw(c1210.09,1679.72) 1312.33,1702.08 ; BAT1.1@1243.46,1789.41 cw(c1215.78,1698.43) BAT1.1@1308.69,1718.76 ; D1.1@1345,1635 cw(c1445.15,1735.16) 1303.66,1741.74 ccw(c1445.15,1735.16) D1.1@1345,1635 ; D1.1@1345,1635 ccw(c1253.73,1543.74) 1238.63,1671.92 cw(c1253.73,1543.74) D1.1@1345,1635 ; BAT1.1@1235.12,1701.72 cw(c1244.5,1622.04) 1301.23,1678.77 ccw(c1244.5,1622.04) BAT1.1@1235.12,1701.72 ; BAT1.1@1236.29,1691.79 cw(c1247.58,1595.94) 1315.82,1664.18 ccw(c1247.58,1595.94) BAT1.1@1236.29,1691.79 ; BAT1.1@1237.46,1681.86 cw(c1250.65,1569.84) 1330.41,1649.59 ccw(c1250.65,1569.84) BAT1.1@1237.46,1681.86 ; BAT1.1@1273.69,1743.13 ccw(c1353.36,1739.43) 1296.97,1683.03 cw(c1353.36,1739.43) BAT1.1@1273.69,1743.13 ; BAT1.1@1283.68,1742.66 ccw(c1383.95,1738) 1312.97,1667.03 cw(c1383.95,1738) BAT1.1@1283.68,1742.66 ; BAT1.1@1293.67,1742.2 ccw(c1414.55,1736.58) 1328.98,1651.02 cw(c1414.55,1736.58) BAT1.1@1293.67,1742.2 ; 1312.1,1657.86 ccw(c1336.28,1692.66) 1343.79,1650.96 cw(c1336.28,1692.66) 1312.1,1657.86 ; 1317.58,1662.42 ccw(c1345,1689.84) 1345,1651.06 cw(c1345,1689.84) 1317.58,1662.42 ; 1323.69,1665.12 ccw(c1352.01,1685.16) 1346.15,1650.97 cw(c1352.01,1685.16) 1323.69,1665.12 ; 1331.93,1644.08 ccw(c1342.33,1659.06) 1345.57,1641.11 cw(c1342.33,1659.06) 1331.93,1644.08
NetC8_2: C8.2 J3.2 R10.1 TEC1.1 U2.2
NetC15_1: C15.1 U3.73 | length 84.8
  Top Layer w10: U3.73@472.1,1340.74 512.85,1300 v1(540,1300)
NetJ1_3: J1.3 R3.1 | length 279.1
  Bottom Layer w10.02: J1.3@760,580 798.5,580 ; R3.1@844,534.5 798.5,580 ; 798.5,580 cw(c798.5,597.97) 782.22,590.37 ccw(c798.5,597.97) 798.5,580 ; 798.5,580 ccw(c798.5,562.03) 782.22,569.63 cw(c798.5,562.03) 798.5,580 ; 820.12,558.38 ccw(c844,582.27) 844,548.49 cw(c844,582.27) 820.12,558.38 ; 823.74,554.76 cw(c804.98,536) 831.51,536 ccw(c804.98,536) 823.74,554.76
NetJ1_4: J1.4 R4.2 | length 310.7
  Bottom Layer w10: R4.2@571,534.5 616.5,580 ; J1.4@660,580 616.5,580 ; 616.5,580 cw(c616.5,553.69) 639.01,567.31 ccw(c616.5,553.69) 616.5,580 ; 616.5,580 ccw(c616.5,606.31) 639.01,592.69 cw(c616.5,606.31) 616.5,580 ; R4.2@571,548.5 ccw(c571,582.3) 594.9,558.4 cw(c571,582.3) R4.2@571,548.5 ; R4.2@583.5,536 cw(c610.06,536) 591.28,554.78 ccw(c610.06,536) R4.2@583.5,536
NetLED1_1: LED1.1 R10.2 | length 464.3
  Top Layer w19.68: LED1.1@561,2201 561,2139 659,2041 862.5,2041 R10.2@864,2039.5 ; 845.51,2041 cw(c845.51,2022.51) 858.59,2035.59 ccw(c845.51,2022.51) 845.51,2041 ; 845.51,2041 ccw(c845.51,2059.49) 858.59,2046.41 cw(c845.51,2059.49) 845.51,2041
NetLED2_2: LED2.2 R13.1 | length 209.5
  Top Layer w19.68: LED2.2@983,304 985,306 R13.1@1100.5,306 ; 1080.51,306 cw(c1080.51,287.51) 1093.59,300.59 ccw(c1080.51,287.51) 1080.51,306 ; 1080.51,306 ccw(c1080.51,324.49) 1093.59,311.41 cw(c1080.51,324.49) 1080.51,306 ; LED2.2@987.18,299.82 cw(c1002.09,284.91) 1002.09,306 ccw(c1002.09,284.91) LED2.2@987.18,299.82
NetP1_2: P1.2 TEC2.1 U2.3
NetQ1_1: Q1.1 R7.2 R8.1 | length 466.7
  Top Layer w10: R7.2@439.2,2514.5 494.7,2514.5 500.5,2508.7 R8.1@500.5,2446 ; 469.37,2514.5 cw(c469.37,2544.68) 448.03,2523.34 ccw(c469.37,2544.68) 469.37,2514.5 ; 469.37,2514.5 ccw(c469.37,2484.32) 448.03,2505.66 cw(c469.37,2484.32) 469.37,2514.5 ; 500.5,2476.18 cw(c470.32,2476.18) 491.66,2454.84 ccw(c470.32,2476.18) 500.5,2476.18 ; 500.5,2476.18 ccw(c530.68,2476.18) 509.34,2454.84 cw(c530.68,2476.18) 500.5,2476.18 ; 468.04,2514.5 ccw(c468.04,2542.16) 487.6,2522.6 cw(c468.04,2542.16) 468.04,2514.5 ; 470.46,2514.5 cw(c470.46,2490.26) 487.6,2507.4 ccw(c470.46,2490.26) 470.46,2514.5 ; Q1.1@487.6,2503.46 cw(c456.44,2472.31) 500.5,2472.31 ccw(c456.44,2472.31) Q1.1@487.6,2503.46
NetQ1_3: Q1.3 R6.2 | length 283.2
  Top Layer w10: Q1.3@532.6,2605.55 637.95,2605.55 R6.2@639,2604.5 ; 558.55,2605.55 cw(c558.55,2631.5) 540.2,2613.15 ccw(c558.55,2631.5) 558.55,2605.55 ; 558.55,2605.55 ccw(c558.55,2579.6) 540.2,2597.95 cw(c558.55,2579.6) 558.55,2605.55 ; 607.74,2605.55 ccw(c607.74,2637.26) 630.16,2614.84 cw(c607.74,2637.26) 607.74,2605.55 ; 609.9,2605.55 cw(c609.9,2576.9) 630.16,2597.16 ccw(c609.9,2576.9) 609.9,2605.55
NetR9_2: R9.2 U1.A5 | length 355.8
  Top Layer w11.81: U1.A5@934.21,2364.92 934.21,2419.21 965,2450 1090,2450 1101,2439 ; R9.2@1130.5,2439 1101,2439 ; 1101.01,2439 cw(c1101.01,2411.01) 1120.8,2430.8 ccw(c1101.01,2411.01) 1101.01,2439 ; 1101.01,2439 ccw(c1101.01,2466.99) 1120.8,2447.2 cw(c1101.01,2466.99) 1101.01,2439
NetR11_1: R11.1 U1.B5 | length 442.2
  Top Layer w11.81: U1.B5@816.1,2364.92 v1(816.1,2418.9) ; v1(865,2467.8) 888.2,2491 R11.1@1130.5,2491 ; R11.1@1120.8,2482.8 ccw(c1101.01,2463.01) 1101.01,2491 ccw(c1101.01,2518.99) R11.1@1120.8,2499.2
  Bottom Layer w11.81: v1(816.1,2418.9) v1(865,2467.8)
NetR100_2: R100.2 U1.1 U1.2 U1.3 U1.4
NRST: C5.2 J2.1 K1.2 R1.1 U3.14 | length 4282.9
  Top Layer w10: K1.2@267.79,78.38 ccw(c296.95,80.96) K1.2@289.37,52.68 ; K1.2@274.45,76.59 cw(c259.95,29.4) 307.63,42.18 ; K1.2@277.38,86.15 cw(c266.21,49.79) 302.96,59.63 ; v1(330,80) v1@329.04,79.04 ; U3.14@1045.58,1073.5 1134.08,985 1290,985 1445,830 v1(1445,810) ; 1049.48,52.65 cw(c1086.61,42.7) J2.1@1078.9,80.36 ; 1057.65,44.48 ccw(c1047.7,81.61) J2.1@1085.36,73.9 ; J2.1@1080,75 1025,20 327.54,20 K1.2@268.5,79.04 v1@329.04,79.04 ; 305.17,79.04 cw(c305.17,108.52) 284.15,87.85 ccw(c305.17,108.52) 305.17,79.04 ; 305.17,79.04 ccw(c305.17,49.55) 284.15,70.23 cw(c305.17,49.55) 305.17,79.04 ; 320.24,81.39 ccw(c323.08,91.98) v1@328.56,82.49 ; 320.24,81.39 ccw(c323.08,91.98) v1@328.56,82.49 ; 320.24,81.39 ccw(c323.08,91.98) v1@328.56,82.49 ; 321.89,77.12 ccw(c319.49,86.07) v1@327.51,81.44 ; 321.89,77.12 ccw(c319.49,86.07) v1@327.51,81.44 ; 321.89,77.12 ccw(c319.49,86.07) v1@327.51,81.44 ; v1@329.03,79.04 cw(c329.03,132) 291.28,94.86 ccw(c329.03,132) v1@329.03,79.04 ; v1@329.03,79.04 ccw(c329.03,26.07) 291.28,63.22 cw(c329.03,26.07) v1@329.03,79.04 ; 1038.13,33.13 cw(c1080,-8.74) 1080,50.47 ccw(c1080,-8.74) 1038.13,33.13 ; 1038.13,33.13 ccw(c996.26,75) 1055.47,75 cw(c996.26,75) 1038.13,33.13 ; J2.1@1055.2,50.2 cw(c1080,25.4) 1080,60.47 ccw(c1080,25.4) J2.1@1055.2,50.2 ; J2.1@1055.2,50.2 ccw(c1030.4,75) 1065.47,75 cw(c1030.4,75) J2.1@1055.2,50.2 ; K1.2@275.2,56.48 cw(c275.2,18.18) 302.28,45.26 ccw(c275.2,18.18) K1.2@275.2,56.48 ; K1.2@287.76,79.04 ccw(c334.23,79.04) 301.37,46.17 cw(c334.23,79.04) K1.2@287.76,79.04 ; K1.2@297.76,79.04 ccw(c368.38,79.04) 318.44,29.1 cw(c368.38,79.04) K1.2@297.76,79.04 ; 320.74,79.04 ccw(c320.74,89.26) 327.97,82.03 cw(c320.74,89.26) 320.74,79.04
  Bottom Layer w10: v1(330,80) 369.5,119.5 R1.1@369.5,191 472,191 C5.2@473,190 ; J2.1@1080,75 1080,140 1190,250 1340,250 1445,355 v1(1445,810) ; 369.5,160.82 cw(c399.68,160.82) 378.34,182.16 ccw(c399.68,160.82) 369.5,160.82 ; 369.5,160.82 ccw(c339.32,160.82) 360.66,182.16 cw(c339.32,160.82) 369.5,160.82 ; 401.18,191 cw(c401.18,221.18) 379.84,199.84 ccw(c401.18,221.18) 401.18,191 ; 401.18,191 ccw(c401.18,160.82) 379.84,182.16 cw(c401.18,160.82) 401.18,191 ; 1080,110.07 cw(c1044.93,110.07) 1069.73,85.27 ccw(c1044.93,110.07) 1080,110.07 ; 1080,110.07 ccw(c1115.07,110.07) 1090.27,85.27 cw(c1115.07,110.07) 1080,110.07 ; 1080,134.21 cw(c1020.79,134.21) 1062.66,92.34 ccw(c1020.79,134.21) 1080,134.21 ; 1080,134.21 ccw(c1139.21,134.21) 1097.34,92.34 cw(c1139.21,134.21) 1080,134.21 ; 442.44,191 cw(c442.44,163.44) 461.93,182.93 ccw(c442.44,163.44) 442.44,191 ; 447.27,191 ccw(c447.27,211.73) 461.93,197.07 cw(c447.27,211.73) 447.27,191
OSC_IN: C1.1 U3.12 Y1.2 | length 529.2
  Top Layer w10: U3.12@1017.74,1045.66 1095,968.4 1095,822.12 ; Y1.2@1100.11,801.09 ccw(c1080.29,807.41) 1095,822.12 ; Y1.2@1116.03,817.01 cw(c1109.72,836.83) 1095,822.12 ; Y1.2@1123.48,793.64 1095,822.12
  Bottom Layer w10: Y1.2@1123.48,793.64 1162.12,755 1170,755 C1.1@1205,720 ; 1187.93,737.07 cw(c1170.86,720) 1195,720 ccw(c1170.86,720) 1187.93,737.07 ; 1187.93,737.07 ccw(c1205,754.14) 1205,730 cw(c1205,754.14) 1187.93,737.07
OSC_OUT: C2.1 U3.13 Y1.1 | length 842.1
  Top Layer w10: U3.13@1031.66,1059.58 1126.23,965 1223.83,965 ; Y1.1@1234.99,932.51 ccw(c1196.16,937.33) 1223.83,965 ; Y1.1@1244.92,931.28 ccw(c1221.92,934.13) 1238.31,950.52 ccw(c1254.7,966.91) Y1.1@1257.55,943.91 ; Y1.1@1256.32,953.83 cw(c1251.5,992.67) 1223.83,965 ; Y1.1@1259.34,929.49 1223.83,965
  Bottom Layer w10: Y1.1@1259.34,929.49 1259.34,925.66 C2.1@1335,850 ; C2.1@1335,855 C2.1@1340,855 ; 1317.93,867.07 cw(c1300.86,850) 1325,850 ccw(c1300.86,850) 1317.93,867.07 ; 1317.93,867.07 ccw(c1335,884.14) 1335,860 cw(c1335,884.14) 1317.93,867.07 ; Y1.1@1259.34,904.96 cw(c1259.34,854.99) 1294.67,890.33 ccw(c1259.34,854.99) Y1.1@1259.34,904.96 ; Y1.1@1273.86,929.49 ccw(c1318.18,929.49) 1286.84,898.16 cw(c1318.18,929.49) Y1.1@1273.86,929.49 ; Y1.1@1283.86,929.49 ccw(c1352.32,929.49) 1303.91,881.09 cw(c1352.32,929.49) Y1.1@1283.86,929.49
PA0: K2.2 P6.25 R12.2 U3.23 | length 3356.6
  Top Layer w10: U3.23@1170.85,1198.77 1204.62,1165 1260,1165 1325,1230 1570,1230 1590,1210 1665,1210 P6.25@1715,1260 ; K2.2@1203.5,79.04 v1@1254.04,79.04 ; v1(1255,80) v1@1254.04,79.04 ; 1684.48,1237.65 cw(c1721.61,1227.7) P6.25@1713.9,1265.36 ; 1692.65,1229.48 ccw(c1682.7,1266.61) P6.25@1720.36,1258.9 ; 1245.24,81.39 ccw(c1248.08,91.98) v1@1253.56,82.49 ; 1245.24,81.39 ccw(c1248.08,91.98) v1@1253.56,82.49 ; 1245.24,81.39 ccw(c1248.08,91.98) v1@1253.56,82.49 ; 1246.89,77.12 ccw(c1244.49,86.07) v1@1252.51,81.44 ; 1246.89,77.12 ccw(c1244.49,86.07) v1@1252.51,81.44 ; 1246.89,77.12 ccw(c1244.49,86.07) v1@1252.51,81.44 ; v1@1254.04,79.04 cw(c1254.04,110.35) 1228.55,92.15 ccw(c1254.04,110.35) v1@1254.04,79.04 ; v1@1254.04,79.04 ccw(c1254.04,47.72) 1228.55,65.93 cw(c1254.04,47.72) v1@1254.04,79.04 ; 1673.13,1218.13 cw(c1715,1176.26) 1715,1235.47 ccw(c1715,1176.26) 1673.13,1218.13 ; 1673.13,1218.13 ccw(c1631.26,1260) 1690.47,1260 cw(c1631.26,1260) 1673.13,1218.13 ; 1690.2,1235.2 cw(c1715,1210.4) 1715,1245.47 ccw(c1715,1210.4) 1690.2,1235.2 ; 1690.2,1235.2 ccw(c1665.4,1260) 1700.47,1260 cw(c1665.4,1260) 1690.2,1235.2 ; 1245.74,79.04 ccw(c1245.74,89.26) 1252.97,82.03 cw(c1245.74,89.26) 1245.74,79.04
  Bottom Layer w10: v1(1255,80) 1325,80 1389.5,144.5 R12.2@1389.5,190.48 1505.48,190.48 1525,210 1655,210 1665,220 1665,1210 P6.25@1715,1260 ; 1684.48,1237.65 cw(c1721.61,1227.7) P6.25@1713.9,1265.36 ; 1692.65,1229.48 ccw(c1682.7,1266.61) P6.25@1720.36,1258.9 ; 1389.5,160.31 cw(c1419.68,160.31) 1398.34,181.65 ccw(c1419.68,160.31) 1389.5,160.31 ; 1389.5,160.31 ccw(c1359.32,160.31) 1380.66,181.65 cw(c1359.32,160.31) 1389.5,160.31 ; 1421.18,190.48 cw(c1421.18,220.66) 1399.84,199.32 ccw(c1421.18,220.66) 1421.18,190.48 ; 1421.18,190.48 ccw(c1421.18,160.31) 1399.84,181.65 cw(c1421.18,160.31) 1421.18,190.48 ; 1673.13,1218.13 cw(c1715,1176.26) 1715,1235.47 ccw(c1715,1176.26) 1673.13,1218.13 ; 1673.13,1218.13 ccw(c1631.26,1260) 1690.47,1260 cw(c1631.26,1260) 1673.13,1218.13 ; 1690.2,1235.2 cw(c1715,1210.4) 1715,1245.47 ccw(c1715,1210.4) 1690.2,1235.2 ; 1690.2,1235.2 ccw(c1665.4,1260) 1700.47,1260 cw(c1665.4,1260) 1690.2,1235.2
PA1: P6.26 R13.2 U3.24 | length 2662.5
  Top Layer w10: R13.2@1169.5,306 1499,306 v1(1500,305) ; U3.24@1184.77,1212.69 1212.47,1185 1250,1185 1325,1260 P6.26@1615,1260 ; 1201.18,306 cw(c1201.18,336.18) 1179.84,314.84 ccw(c1201.18,336.18) 1201.18,306 ; 1201.18,306 ccw(c1201.18,275.82) 1179.84,297.16 cw(c1201.18,275.82) 1201.18,306 ; 1555.79,1260 cw(c1555.79,1200.79) 1597.66,1242.66 ccw(c1555.79,1200.79) 1555.79,1260 ; 1555.79,1260 ccw(c1555.79,1319.21) 1597.66,1277.34 cw(c1555.79,1319.21) 1555.79,1260 ; 1579.93,1260 cw(c1579.93,1224.93) 1604.73,1249.73 ccw(c1579.93,1224.93) 1579.93,1260 ; 1579.93,1260 ccw(c1579.93,1295.07) 1604.73,1270.27 cw(c1579.93,1295.07) 1579.93,1260 ; 1490.65,306 cw(c1490.65,295.65) 1497.97,302.97 ccw(c1490.65,295.65) 1490.65,306
  Bottom Layer w10: v1(1500,305) 1510,305 1570,365 1570,1215 P6.26@1615,1260 ; v1@1502.49,303.56 cw(c1516.71,295.35) 1512.46,311.21 ; 1584.48,1237.65 cw(c1621.61,1227.7) P6.26@1613.9,1265.36 ; 1592.65,1229.48 ccw(c1582.7,1266.61) P6.26@1620.36,1258.9 ; 1573.13,1218.13 cw(c1615,1176.26) 1615,1235.47 ccw(c1615,1176.26) 1573.13,1218.13 ; 1573.13,1218.13 ccw(c1531.26,1260) 1590.47,1260 cw(c1531.26,1260) 1573.13,1218.13 ; 1590.2,1235.2 cw(c1615,1210.4) 1615,1245.47 ccw(c1615,1210.4) 1590.2,1235.2 ; 1590.2,1235.2 ccw(c1565.4,1260) 1600.47,1260 cw(c1565.4,1260) 1590.2,1235.2 ; v1@1500,307.87 ccw(c1500,338.95) 1521.98,316.98 cw(c1500,338.95) v1@1500,307.87
PA2: P6.27 U3.25 | length 952.9
  Top Layer w10: U3.25@1198.69,1226.61 1252.08,1280 1500,1280 1530,1310 1665,1310 P6.27@1715,1360 ; 1684.48,1337.65 cw(c1721.61,1327.7) P6.27@1713.9,1365.36 ; 1692.65,1329.48 ccw(c1682.7,1366.61) P6.27@1720.36,1358.9 ; 1673.13,1318.13 cw(c1715,1276.26) 1715,1335.47 ccw(c1715,1276.26) 1673.13,1318.13 ; 1673.13,1318.13 ccw(c1631.26,1360) 1690.47,1360 cw(c1631.26,1360) 1673.13,1318.13 ; 1690.2,1335.2 cw(c1715,1310.4) 1715,1345.47 ccw(c1715,1310.4) 1690.2,1335.2 ; 1690.2,1335.2 ccw(c1665.4,1360) 1700.47,1360 cw(c1665.4,1360) 1690.2,1335.2
PA3: P6.28 U3.26 | length 742.7
  Top Layer w10: U3.26@1198.69,1312.9 1211.6,1300 1460,1300 1520,1360 P6.28@1615,1360 ; 1555.79,1360 cw(c1555.79,1300.79) 1597.66,1342.66 ccw(c1555.79,1300.79) 1555.79,1360 ; 1555.79,1360 ccw(c1555.79,1419.21) 1597.66,1377.34 cw(c1555.79,1419.21) 1555.79,1360 ; 1579.93,1360 cw(c1579.93,1324.93) 1604.73,1349.73 ccw(c1579.93,1324.93) 1579.93,1360 ; 1579.93,1360 ccw(c1579.93,1395.07) 1604.73,1370.27 cw(c1579.93,1395.07) 1579.93,1360
PA4: P6.29 U3.29 | length 933.3
  Top Layer w10: U3.29@1156.94,1354.66 1237.28,1435 1540,1435 1565,1410 1675,1410 ; 1689.01,1443.28 cw(c1732.2,1437.83) P6.29@1705.51,1472.22 ; 1697.21,1430.71 ccw(c1689.08,1461.05) P6.29@1720.47,1459.78 ; P6.29@1715,1460 1715,1450 1675,1410 ; 1675,1410 ccw(c1635.86,1449.14) 1690.7,1456.67 cw(c1635.86,1449.14) 1675,1410 ; 1689.24,1424.24 ccw(c1660.91,1452.58) 1700.61,1458.03 cw(c1660.91,1452.58) 1689.24,1424.24 ; 1690.2,1425.2 cw(c1715,1400.4) 1715,1435.47 ccw(c1715,1400.4) 1690.2,1425.2
PA5: P6.30 U3.30 | length 781.9
  Top Layer w10: U3.30@1143.01,1368.58 1239.43,1465 1610,1465 P6.30@1615,1460 ; 1567.86,1465 cw(c1567.86,1412.86) 1604.73,1449.73 ccw(c1567.86,1412.86) 1567.86,1465 ; 1567.86,1465 ccw(c1567.86,1507.14) 1597.66,1477.34 cw(c1567.86,1507.14) 1567.86,1465 ; 1543.71,1465 cw(c1543.71,1388.71) 1597.66,1442.66 ccw(c1543.71,1388.71) 1543.71,1465
PA6: P6.31 U3.31 | length 1040.3
  Top Layer w10.02: U3.31@1129.1,1382.5 1256.6,1510 1665,1510 P6.31@1715,1560 ; 1684.53,1537.77 cw(c1721.59,1527.84) P6.31@1713.89,1565.43 ; 1692.77,1529.53 ccw(c1682.84,1566.59) P6.31@1720.43,1558.89 ; 1673.15,1518.15 cw(c1715,1476.29) 1715,1535.48 ccw(c1715,1476.29) 1673.15,1518.15 ; 1673.15,1518.15 ccw(c1631.29,1560) 1690.48,1560 cw(c1631.29,1560) 1673.15,1518.15 ; 1690.25,1535.25 cw(c1715,1510.5) 1715,1545.5 ccw(c1715,1510.5) 1690.25,1535.25 ; 1690.25,1535.25 ccw(c1665.5,1560) 1700.5,1560 cw(c1665.5,1560) 1690.25,1535.25
PA7: P6.32 U3.32 | length 863.5
  Top Layer w10.02: U3.32@1115.17,1396.42 1278.75,1560 P6.32@1615,1560 ; 1555.81,1560 cw(c1555.81,1500.81) 1597.66,1542.66 ccw(c1555.81,1500.81) 1555.81,1560 ; 1555.81,1560 ccw(c1555.81,1619.19) 1597.66,1577.34 cw(c1555.81,1619.19) 1555.81,1560 ; 1580,1560 cw(c1580,1525) 1604.75,1549.75 ccw(c1580,1525) 1580,1560 ; 1580,1560 ccw(c1580,1595) 1604.75,1570.25 cw(c1580,1595) 1580,1560
PA8: P7.32 U3.67 | length 979.6
  Top Layer w10: P7.32@49.64,1561.1 cw(c87.3,1553.39) 77.35,1590.52 ; P7.32@55,1560 105,1610 369.88,1610 U3.67@555.62,1424.26 ; P7.32@56.1,1554.64 ccw(c48.39,1592.3) 85.52,1582.35 ; 79.8,1584.8 cw(c55,1609.6) 55,1574.53 ccw(c55,1609.6) 79.8,1584.8 ; 79.8,1584.8 ccw(c104.6,1560) 69.53,1560 cw(c104.6,1560) 79.8,1584.8 ; 96.87,1601.87 cw(c55,1643.74) 55,1584.53 ccw(c55,1643.74) 96.87,1601.87 ; 96.87,1601.87 ccw(c138.74,1560) 79.53,1560 cw(c138.74,1560) 96.87,1601.87
PA9: P7.31 U3.68 | length 744.9
  Top Layer w10: P7.31@155,1560 392.03,1560 U3.68@541.7,1410.34 ; 190.07,1560 cw(c190.07,1595.07) 165.27,1570.27 ccw(c190.07,1595.07) 190.07,1560 ; 190.07,1560 ccw(c190.07,1524.93) 165.27,1549.73 cw(c190.07,1524.93) 190.07,1560 ; 214.21,1560 cw(c214.21,1619.21) 172.34,1577.34 ccw(c214.21,1619.21) 214.21,1560 ; 214.21,1560 ccw(c214.21,1500.79) 172.34,1542.66 cw(c214.21,1500.79) 214.21,1560
PA10: P7.30 U3.69 | length 917.7
  Top Layer w10: P7.30@49.64,1461.1 cw(c87.3,1453.39) 77.35,1490.52 ; P7.30@55,1460 100,1505 419.2,1505 U3.69@527.78,1396.42 ; P7.30@56.1,1454.64 ccw(c48.39,1492.3) 85.52,1482.35 ; 79.8,1484.8 cw(c55,1509.6) 55,1474.53 ccw(c55,1509.6) 79.8,1484.8 ; 79.8,1484.8 ccw(c104.6,1460) 69.53,1460 cw(c104.6,1460) 79.8,1484.8 ; 96.87,1501.87 cw(c55,1543.74) 55,1484.53 ccw(c55,1543.74) 96.87,1501.87 ; 96.87,1501.87 ccw(c138.74,1460) 79.53,1460 cw(c138.74,1460) 96.87,1501.87
PA11: P7.29 U1.A7 U1.B7 U3.70 | length 1814.6
  Top Layer w11.81: P7.29@155,1460 v1(380,1460) 436.36,1460 U3.70@513.86,1382.5 ; U1.A7@875.16,2364.92 875.16,2400.16 885,2410 905,2410 914.53,2400.47 U1.B7@914.53,2364.92 v1(914.53,2305) ; 212.03,1460 cw(c212.03,1517.03) 171.7,1476.7 ccw(c212.03,1517.03) 212.03,1460 ; 212.03,1460 ccw(c212.03,1402.97) 171.7,1443.3 cw(c212.03,1402.97) 212.03,1460
  Bottom Layer w11.81: v1(380,1460) 670,1750 670,1995 914.53,2239.53 v1(914.53,2305)
PA12: P7.28 R6.1 U1.A6 U1.B6 U3.71 | length 2496.2
  Top Layer w11.81: 84.76,1391.6 ccw(c95.45,1351.72) P7.28@55,1360 ; 86.6,1389.76 cw(c46.72,1400.45) P7.28@55,1360 ; v1@300,1409.91 104.91,1409.91 P7.28@55,1360 ; v1(300,1410) 324.91,1410 325,1409.91 458.62,1409.91 U3.71@499.94,1368.58 ; R6.1@639,2535.5 639,2501 660,2480 805,2480 855.47,2429.53 U1.B6@855.47,2364.92 855.47,2329.53 ; v1@874.91,2321.97 cw(c873.79,2347.84) 855.47,2329.53 ; v1@875.04,2321.97 ccw(c875.6,2349.4) 895,2330 ; U1.A6@894.84,2364.92 895,2364.76 895,2330 ; 95.33,1400.33 cw(c55,1440.65) 55,1383.62 ccw(c55,1440.65) 95.33,1400.33 ; 95.33,1400.33 ccw(c135.65,1360) 78.62,1360 cw(c135.65,1360) 95.33,1400.33 ; 639,2506.01 cw(c666.99,2506.01) 647.2,2525.8 ccw(c666.99,2506.01) 639,2506.01 ; 639,2506.01 ccw(c611.01,2506.01) 630.8,2525.8 cw(c611.01,2506.01) 639,2506.01 ; 855.47,2329.53 865,2320 v1(875,2320) 885,2320 895,2330
  Bottom Layer w11.81: v1(300,1410) 650,1760 650,2035 875,2260 v1(875,2320)
PA13: J2.4 P7.27 U3.72 | length 3025.1
  Top Layer w10: P7.27@155,1360 213,1360 ; U3.72@486.02,1354.66 453.68,1387 240,1387 213,1360 ; 189.35,1360 cw(c189.35,1393.35) 165.42,1370.12 ccw(c189.35,1393.35) 189.35,1360 ; 189.35,1360 ccw(c189.35,1326.65) 165.42,1349.88 cw(c189.35,1326.65) 189.35,1360 ; 213,1360 cw(c213,1416.31) 172.6,1377.08 ccw(c213,1416.31) 213,1360 ; 213,1360 ccw(c213,1303.69) 172.6,1342.92 cw(c213,1303.69) 213,1360
  Bottom Layer w10: P7.27@149.64,1358.9 ccw(c187.3,1366.61) 177.35,1329.48 ; P7.27@155,1360 270,1245 270,405 400,275 675,275 780,170 J2.4@780,75 ; P7.27@156.1,1365.36 cw(c148.39,1327.7) 185.52,1337.65 ; 179.8,1335.2 cw(c204.6,1360) 169.53,1360 ccw(c204.6,1360) 179.8,1335.2 ; 179.8,1335.2 ccw(c155,1310.4) 155,1345.47 cw(c155,1310.4) 179.8,1335.2 ; 196.87,1318.13 cw(c238.74,1360) 179.53,1360 ccw(c238.74,1360) 196.87,1318.13 ; 196.87,1318.13 ccw(c155,1276.26) 155,1335.47 cw(c155,1276.26) 196.87,1318.13 ; 780,110.07 cw(c744.93,110.07) 769.73,85.27 ccw(c744.93,110.07) 780,110.07 ; 780,110.07 ccw(c815.07,110.07) 790.27,85.27 cw(c815.07,110.07) 780,110.07 ; 780,134.21 cw(c720.79,134.21) 762.66,92.34 ccw(c720.79,134.21) 780,134.21 ; 780,134.21 ccw(c839.21,134.21) 797.34,92.34 cw(c839.21,134.21) 780,134.21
